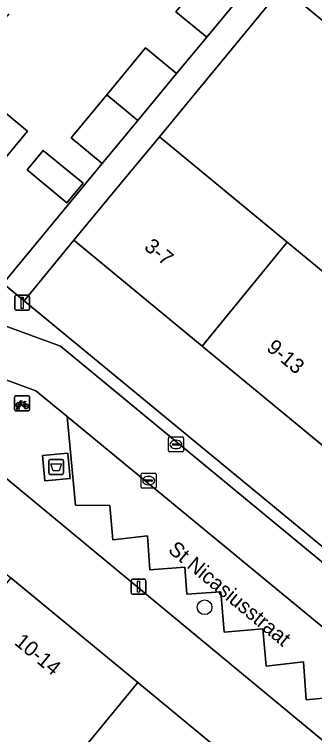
# Model space of a CAD drawing. Extents: x 162073 to 163043, y 381818 to 382561.
# Drawn here: x 162379.75 to 162399.8, y 382101.18 to 382149.28 of the extents above; entities that cross this region are included whole.
import ezdxf

# ---------------------------------------------------------------- set-up
doc = ezdxf.new("R2010")
doc.units = 0
for name, color, linetype in [('IMGEO_Afval_apart_plaats', 7, 'Continuous'), ('IMGEO_Boom', 7, 'Continuous'), ('IMGEO_Erf', 7, 'Continuous'), ('IMGEO_Fietsenrek', 7, 'Continuous'), ('IMGEO_Kolk', 7, 'Continuous'), ('IMGEO_Lichtmast', 7, 'Continuous'), ('IMGEO_Openbare_ruimte_label', 7, 'Continuous'), ('IMGEO_Pand', 7, 'Continuous'), ('IMGEO_Pand_nummerreeks', 7, 'Continuous'), ('IMGEO_Parkeervlak_open', 7, 'Continuous'), ('IMGEO_Rijbaan_lokaal_open', 7, 'Continuous'), ('IMGEO_Voetpad_gesloten', 7, 'Continuous'), ('IMGEO_Voetpad_open', 7, 'Continuous')]:
    doc.layers.add(name, color=color, linetype=linetype)

msp = doc.modelspace()

# ---------------------------------------------------------------- linework, layer by layer
at = {"layer": 'IMGEO_Afval_apart_plaats'}
for p, q in [((162382.04, 382118.659), (162382.04, 382119.459)), ((162382.04, 382119.459), (162382.04, 382118.659)), ((162382.14, 382119.559), (162382.93, 382119.559)), ((162382.93, 382119.559), (162382.14, 382119.559)), ((162383.03, 382119.459), (162383.03, 382118.659)), ((162383.03, 382118.659), (162383.03, 382119.459)), ((162382.93, 382118.559), (162382.14, 382118.559)), ((162382.14, 382118.559), (162382.93, 382118.559))]:
    msp.add_line(p, q, dxfattribs=at)
msp.add_lwpolyline([(162382.183, 382119.273), (162382.887, 382119.273), (162382.738, 382118.803), (162382.332, 382118.803), (162382.183, 382119.273)], dxfattribs=at)
for centre, start, end in [((162382.14, 382119.459), 90, 180), ((162382.14, 382119.459), 90, 180), ((162382.93, 382119.459), 0, 90), ((162382.93, 382119.459), 360, 90), ((162382.14, 382118.659), 180, 270), ((162382.14, 382118.659), 180, 270), ((162382.93, 382118.659), 270, 0), ((162382.93, 382118.659), 270, 0)]:
    msp.add_arc(centre, 0.1, start, end, dxfattribs=at)
at = {"layer": 'IMGEO_Boom'}
msp.add_circle((162392.451, 382109.684), 0.489, dxfattribs=at)
at = {"layer": 'IMGEO_Erf'}
for points in [[(162363.474, 382144.097), (162379.006, 382131.297), (162385.618, 382139.32), (162383.544, 382141.028), (162385.913, 382143.906), (162388.503, 382147.051), (162390.577, 382145.343), (162392.595, 382147.754), (162390.521, 382149.462), (162392.89, 382152.34), (162395.48, 382155.485), (162397.554, 382153.777), (162399.374, 382155.928), (162397.3, 382157.636), (162399.67, 382160.515)], [(162379.373, 382149.317), (162376.035, 382145.271), (162380.615, 382141.493), (162377.647, 382137.895), (162365.645, 382147.796), (162368.566, 382151.337)]]:
    msp.add_lwpolyline(points, dxfattribs=at)
for points in [[(162426.82, 382110.258), (162431.897, 382106.068), (162440.381, 382099.065), (162448.864, 382092.063), (162456.35, 382101.275), (162460.128, 382098.157), (162453.876, 382090.581), (162458.753, 382086.556), (162457.449, 382084.977), (162457.546, 382084.897), (162465.734, 382094.868), (162397.649, 382151.094), (162389.437, 382141.114), (162397.963, 382134.077), (162406.447, 382127.074), (162414.93, 382120.072), (162423.413, 382113.07), (162423.685, 382112.846), (162430.242, 382120.791), (162433.377, 382118.204)], [(162383.253, 382136.696), (162380.594, 382138.89), (162381.676, 382140.201), (162384.335, 382138.007)], [(162417.75, 382106.108), (162409.267, 382113.11), (162400.782, 382120.113), (162392.297, 382127.116), (162383.724, 382134.193), (162380.395, 382130.153), (162448.544, 382073.992), (162451.833, 382077.976), (162443.204, 382085.098), (162434.72, 382092.101), (162426.235, 382099.105)], [(162374.058, 382122.534), (162370.927, 382118.714), (162379.513, 382111.639), (162387.985, 382104.658), (162396.457, 382097.677), (162404.928, 382090.697), (162413.399, 382083.717), (162421.871, 382076.736), (162430.342, 382069.755), (162438.929, 382062.68), (162442.197, 382066.248), (162438.394, 382069.293)]]:
    msp.add_lwpolyline(points, close=True, dxfattribs=at)
at = {"layer": 'IMGEO_Fietsenrek'}
for p, q in [((162379.76, 382122.878), (162379.76, 382123.719)), ((162379.76, 382123.719), (162379.76, 382122.878)), ((162379.835, 382123.803), (162380.676, 382123.803)), ((162380.676, 382123.803), (162379.835, 382123.803)), ((162380.76, 382123.728), (162380.76, 382122.887)), ((162380.76, 382122.887), (162380.76, 382123.728)), ((162379.998, 382123.059), (162379.997, 382123.063)), ((162380.029, 382123.07), (162380.03, 382123.063)), ((162380.447, 382123.352), (162380.483, 382123.257)), ((162380.685, 382122.803), (162379.844, 382122.803)), ((162379.844, 382122.803), (162380.685, 382122.803)), ((162379.887, 382122.887), (162379.926, 382123.047)), ((162379.921, 382122.887), (162379.887, 382122.887)), ((162379.956, 382123.035), (162379.921, 382122.887)), ((162380.039, 382122.887), (162380.005, 382123.029)), ((162380.037, 382123.033), (162380.072, 382122.887)), ((162380.072, 382122.887), (162380.039, 382122.887))]:
    msp.add_line(p, q, dxfattribs=at)
for points in [[(162380.094, 382123.277), (162380.042, 382123.187), (162380.002, 382123.162), (162380.003, 382123.209), (162380.058, 382123.303)], [(162380.073, 382123.329), (162380.168, 382123.493), (162380.254, 382123.479), (162380.256, 382123.47), (162380.2, 382123.459), (162380.173, 382123.414), (162380.429, 382123.373)], [(162380.369, 382123.085), (162380.319, 382123.085), (162380.128, 382123.336), (162380.109, 382123.304)], [(162380.416, 382123.348), (162380.159, 382123.389), (162380.142, 382123.36), (162380.309, 382123.14), (162380.416, 382123.348)], [(162380.464, 382123.25), (162380.434, 382123.327), (162380.325, 382123.109), (162380.368, 382123.109)], [(162380.398, 382123.109), (162380.518, 382123.108), (162380.474, 382123.222)], [(162380.494, 382123.229), (162380.549, 382123.084), (162380.399, 382123.084)], [(162380.429, 382123.373), (162380.454, 382123.422), (162380.448, 382123.426), (162380.425, 382123.43), (162380.413, 382123.437), (162380.412, 382123.44), (162380.414, 382123.445), (162380.509, 382123.43), (162380.511, 382123.42), (162380.501, 382123.407), (162380.489, 382123.401), (162380.475, 382123.407), (162380.447, 382123.352)]]:
    msp.add_lwpolyline(points, dxfattribs=at)
for centre, radius, start, end in [((162379.838, 382123.725), 0.0779, 92.4484, 184.2845), ((162379.838, 382123.725), 0.0779, 92.4484, 184.2845), ((162380.682, 382123.725), 0.0779, 2.4484, 94.2845), ((162380.682, 382123.725), 0.0779, 2.4484, 94.2845), ((162380, 382123.188), 0.159, 62.6766, 242.1369), ((162380, 382123.188), 0.129, 63.3192, 238.903), ((162379.98, 382123.059), 0.0499, 12.8025, 158.6934), ((162379.98, 382123.059), 0.0174, 12.8025, 163.4502), ((162380, 382123.188), 0.129, 253.415, 269.0204), ((162380, 382123.188), 0.129, 283.6043, 43.4302), ((162380, 382123.188), 0.159, 283.5766, 46.6042), ((162380.527, 382123.104), 0.159, 113.3408, 178.3217), ((162380.527, 382123.104), 0.159, 187.0065, 105.7708), ((162380.527, 382123.104), 0.129, 113.923, 177.9556), ((162380.527, 382123.104), 0.129, 188.6715, 104.5883), ((162379.838, 382122.881), 0.0779, 182.4484, 274.2845), ((162379.838, 382122.881), 0.0779, 182.4484, 274.2845), ((162380, 382123.188), 0.159, 253.9967, 271.7867), ((162380.682, 382122.881), 0.0779, 272.4484, 4.2845), ((162380.682, 382122.881), 0.0779, 272.4484, 4.2845)]:
    msp.add_arc(centre, radius, start, end, dxfattribs=at)
at = {"layer": 'IMGEO_Kolk'}
for p, q in [((162390.035, 382120.132), (162390.035, 382120.984)), ((162390.11, 382121.058), (162390.962, 382121.058)), ((162390.523, 382120.838), (162390.548, 382120.838)), ((162391.036, 382120.984), (162391.036, 382120.132)), ((162390.294, 382120.552), (162390.294, 382120.564)), ((162390.732, 382120.515), (162390.334, 382120.515)), ((162390.337, 382120.601), (162390.735, 382120.601)), ((162390.546, 382120.278), (162390.521, 382120.278)), ((162390.778, 382120.564), (162390.778, 382120.552)), ((162390.962, 382120.058), (162390.11, 382120.058)), ((162388.217, 382117.716), (162388.217, 382118.568)), ((162388.292, 382118.642), (162389.144, 382118.642)), ((162388.705, 382118.422), (162388.73, 382118.422)), ((162389.218, 382118.568), (162389.218, 382117.716)), ((162388.476, 382118.136), (162388.476, 382118.148)), ((162388.914, 382118.099), (162388.516, 382118.099)), ((162388.519, 382118.185), (162388.917, 382118.185)), ((162388.728, 382117.862), (162388.703, 382117.862)), ((162388.96, 382118.148), (162388.96, 382118.136)), ((162389.144, 382117.642), (162388.292, 382117.642))]:
    msp.add_line(p, q, dxfattribs=at)
for points in [[(162390.035, 382120.132), (162390.035, 382120.984)], [(162390.11, 382121.058), (162390.962, 382121.058)], [(162391.036, 382120.984), (162391.036, 382120.132)], [(162390.962, 382120.058), (162390.11, 382120.058)], [(162388.217, 382117.716), (162388.217, 382118.568)], [(162388.292, 382118.642), (162389.144, 382118.642)], [(162389.218, 382118.568), (162389.218, 382117.716)], [(162389.144, 382117.642), (162388.292, 382117.642)]]:
    msp.add_lwpolyline(points, dxfattribs=at)
for centre, radius, start, end in [((162390.112, 382120.982), 0.0765, 91.552, 178.448), ((162390.112, 382120.982), 0.0765, 91.552, 178.448), ((162390.96, 382120.982), 0.0765, 1.552, 88.448), ((162390.96, 382120.982), 0.0765, 1.552, 88.448), ((162390.334, 382120.561), 0.0403, 85.8775, 175.7526), ((162390.331, 382120.551), 0.0366, 178.938, 274.7102), ((162390.735, 382120.558), 0.043, 264.8664, 352.4533), ((162390.739, 382120.563), 0.0386, 1.7309, 96.639), ((162390.112, 382120.134), 0.0765, 181.552, 268.448), ((162390.112, 382120.134), 0.0765, 181.552, 268.448), ((162390.96, 382120.134), 0.0765, 271.552, 358.448), ((162390.96, 382120.134), 0.0765, 271.552, 358.448), ((162388.294, 382118.566), 0.0765, 91.552, 178.448), ((162388.294, 382118.566), 0.0765, 91.552, 178.448), ((162389.142, 382118.566), 0.0765, 1.552, 88.448), ((162389.142, 382118.566), 0.0765, 1.552, 88.448), ((162388.516, 382118.145), 0.0403, 85.8775, 175.7526), ((162388.513, 382118.135), 0.0366, 178.938, 274.7102), ((162388.917, 382118.142), 0.043, 264.8664, 352.4533), ((162388.921, 382118.147), 0.0386, 1.7309, 96.639), ((162388.294, 382117.718), 0.0765, 181.552, 268.448), ((162388.294, 382117.718), 0.0765, 181.552, 268.448), ((162389.142, 382117.718), 0.0765, 271.552, 358.448), ((162389.142, 382117.718), 0.0765, 271.552, 358.448)]:
    msp.add_arc(centre, radius, start, end, dxfattribs=at)
for centre, major_axis, ratio, start_param, end_param in [((162390.522, 382120.558), (-0.387, 0.002), 0.722429, 4.712389, 7.853982), ((162390.547, 382120.558), (-0.39, 0.002), 0.717154, 1.570796, 4.712389), ((162388.704, 382118.142), (-0.387, 0.002), 0.722429, 4.712389, 7.853982), ((162388.729, 382118.142), (-0.39, 0.002), 0.717154, 1.570796, 4.712389)]:
    msp.add_ellipse(centre, major_axis=major_axis, ratio=ratio, start_param=start_param, end_param=end_param, dxfattribs=at)
at = {"layer": 'IMGEO_Lichtmast'}
for p, q in [((162379.769, 382129.623), (162379.769, 382130.423)), ((162379.769, 382130.423), (162379.769, 382129.623)), ((162379.869, 382130.523), (162380.659, 382130.523)), ((162380.659, 382130.523), (162379.869, 382130.523)), ((162380.759, 382130.423), (162380.759, 382129.623)), ((162380.759, 382129.623), (162380.759, 382130.423)), ((162380.659, 382129.523), (162379.869, 382129.523)), ((162379.869, 382129.523), (162380.659, 382129.523)), ((162387.641, 382111.559), (162388.431, 382111.559)), ((162388.431, 382111.559), (162387.641, 382111.559)), ((162387.541, 382110.659), (162387.541, 382111.459)), ((162387.541, 382111.459), (162387.541, 382110.659)), ((162388.531, 382111.459), (162388.531, 382110.659)), ((162388.531, 382110.659), (162388.531, 382111.459)), ((162388.431, 382110.559), (162387.641, 382110.559)), ((162387.641, 382110.559), (162388.431, 382110.559))]:
    msp.add_line(p, q, dxfattribs=at)
for points in [[(162380.189, 382130.398), (162380.339, 382130.398), (162380.339, 382129.648), (162380.189, 382129.648), (162380.189, 382130.398)], [(162387.961, 382111.434), (162388.111, 382111.434), (162388.111, 382110.684), (162387.961, 382110.684), (162387.961, 382111.434)]]:
    msp.add_lwpolyline(points, dxfattribs=at)
for centre, start, end in [((162379.869, 382130.423), 90, 180), ((162379.869, 382130.423), 90, 180), ((162380.659, 382130.423), 0, 90), ((162380.659, 382130.423), 360, 90), ((162379.869, 382129.623), 180, 270), ((162379.869, 382129.623), 180, 270), ((162380.659, 382129.623), 270, 0), ((162380.659, 382129.623), 270, 0), ((162387.641, 382111.459), 90, 180), ((162387.641, 382111.459), 90, 180), ((162388.431, 382111.459), 0, 90), ((162388.431, 382111.459), 360, 90), ((162387.641, 382110.659), 180, 270), ((162387.641, 382110.659), 180, 270), ((162388.431, 382110.659), 270, 0), ((162388.431, 382110.659), 270, 0)]:
    msp.add_arc(centre, 0.1, start, end, dxfattribs=at)
at = {"layer": 'IMGEO_Pand'}
for points in [[(162392.89, 382152.34), (162390.521, 382149.462), (162392.595, 382147.754), (162394.961, 382150.627)], [(162368.566, 382151.337), (162365.645, 382147.796), (162377.647, 382137.895), (162380.615, 382141.493), (162376.035, 382145.271), (162375.737, 382144.939), (162368.82, 382150.661), (162369.049, 382150.938)], [(162387.984, 382142.193), (162390.577, 382145.343), (162388.503, 382147.051), (162385.913, 382143.906)], [(162387.984, 382142.193), (162385.913, 382143.906), (162383.544, 382141.028), (162385.618, 382139.32)], [(162397.963, 382134.077), (162389.437, 382141.114), (162386.907, 382138.049), (162383.724, 382134.193), (162392.297, 382127.116)], [(162383.253, 382136.696), (162384.335, 382138.007), (162381.676, 382140.201), (162380.594, 382138.89)], [(162400.782, 382120.113), (162406.447, 382127.074), (162397.963, 382134.077), (162392.297, 382127.116)], [(162373.743, 382104.635), (162382.215, 382097.655), (162387.985, 382104.658), (162379.513, 382111.639)], [(162396.457, 382097.677), (162387.985, 382104.658), (162382.215, 382097.655), (162380.558, 382095.645), (162389.03, 382088.664), (162390.686, 382090.674)]]:
    msp.add_lwpolyline(points, close=True, dxfattribs=at)
at = {"layer": 'IMGEO_Parkeervlak_open'}
msp.add_lwpolyline([(162443.882, 382072.46), (162383.272, 382122.429), (162383.819, 382116.509), (162386.121, 382116.488), (162386.314, 382114.195), (162388.627, 382114.45), (162388.783, 382112.18), (162391.139, 382112.362), (162391.265, 382110.558), (162393.527, 382110.707), (162393.745, 382108.01), (162396.341, 382108.252), (162396.566, 382105.76), (162399.056, 382106.033), (162399.237, 382103.506), (162401.794, 382103.745)], dxfattribs=at)
at = {"layer": 'IMGEO_Rijbaan_lokaal_open'}
for points in [[(162450.473, 382067.754), (162448.153, 382073.217), (162382.822, 382127.114), (162375.036, 382129.973), (162374.57, 382130.393), (162373.697, 382131.117), (162359.38, 382142.904), (162358.519, 382143.628)], [(162356.428, 382141.01), (162357.272, 382140.243), (162371.197, 382128.843), (162372.287, 382127.917), (162373.341, 382127.019), (162381.182, 382124.132), (162383.272, 382122.429), (162443.882, 382072.46), (162445.4, 382071.193), (162447.637, 382065.739)]]:
    msp.add_lwpolyline(points, dxfattribs=at)
at = {"layer": 'IMGEO_Voetpad_gesloten'}
msp.add_lwpolyline([(162383.305, 382119.986), (162381.619, 382119.817), (162381.768, 382118.136), (162383.472, 382118.283)], close=True, dxfattribs=at)
at = {"layer": 'IMGEO_Voetpad_open'}
for points in [[(162394.961, 382150.627), (162392.595, 382147.754), (162390.577, 382145.343), (162387.984, 382142.193), (162385.618, 382139.32), (162379.006, 382131.297), (162380.395, 382130.153), (162383.724, 382134.193), (162386.907, 382138.049), (162389.437, 382141.114), (162397.649, 382151.094), (162465.734, 382094.868)], [(162453.791, 382069.764), (162453.132, 382070.292), (162452.152, 382071.11), (162448.681, 382073.879), (162448.544, 382073.992), (162380.395, 382130.153), (162379.006, 382131.297), (162363.474, 382144.097)], [(162356.934, 382136.569), (162372.628, 382123.707), (162374.058, 382122.534), (162438.394, 382069.293), (162442.197, 382066.248), (162443.042, 382065.571), (162446.525, 382062.616), (162454.536, 382056.174)], [(162374.57, 382130.393), (162375.036, 382129.973), (162382.822, 382127.114), (162448.153, 382073.217), (162450.473, 382067.754), (162451.851, 382066.605)], [(162401.794, 382103.745), (162399.237, 382103.506), (162399.056, 382106.033), (162396.566, 382105.76), (162396.341, 382108.252), (162393.745, 382108.01), (162393.527, 382110.707), (162391.265, 382110.558), (162391.139, 382112.362), (162388.783, 382112.18), (162388.627, 382114.45), (162386.314, 382114.195), (162386.121, 382116.488), (162383.819, 382116.509), (162383.272, 382122.429), (162381.182, 382124.132), (162373.341, 382127.019), (162372.287, 382127.917), (162372.173, 382127.404), (162371.518, 382126.587)]]:
    msp.add_lwpolyline(points, dxfattribs=at)
msp.add_lwpolyline([(162383.472, 382118.283), (162381.768, 382118.136), (162381.619, 382119.817), (162383.305, 382119.986)], close=True, dxfattribs=at)

# ---------------------------------------------------------------- texts
at = {"layer": 'IMGEO_Openbare_ruimte_label'}
msp.add_text('St Nicasiusstraat', height=1, rotation=320.3558, dxfattribs=at).set_placement((162389.946, 382113.42))
at = {"layer": 'IMGEO_Pand_nummerreeks'}
for s, rotation, p in [('3-7', 320.4638, (162388.348, 382133.644)), ('9-13', 320.4638, (162396.522, 382126.897)), ('10-14', 320.5113, (162379.685, 382107.247))]:
    msp.add_text(s, height=1, rotation=rotation, dxfattribs=at).set_placement(p)

doc.saveas('drawing.dxf')
